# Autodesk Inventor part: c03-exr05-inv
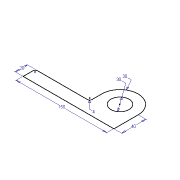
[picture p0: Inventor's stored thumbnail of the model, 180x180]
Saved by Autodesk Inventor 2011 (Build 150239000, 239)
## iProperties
Shininess: 64.0
Length Units: 11269
Angle Units: 11279
Time Units: 11290
Mass Units: 11283
Length Display Precision: 3
Angle Display Precision: 2
Compacted: True
Created: 2002-02
Part Number: c03-exr05-inv
Document SubType Name: Modeling
Density: 1 g/cm^3
Density: 0.0
Volumn: 0.0
Area: 0.0
PropertySet Name: Model Information
Control State: 0
Master: False
Checked Out: False
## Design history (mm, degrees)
sketch "Sketch1"
  geometry: L1 (-66.957, -29.14)-(83.043, -29.14); L2 (83.043, -29.14)-(83.043, 10.86); L3 (23.043, 10.86)-(23.043, -5.14); L4 (19.043, -9.14)-(-62.957, -9.14); L5 (-66.957, -13.14)-(-66.957, -29.14); C1 r 15 at (53.043, 10.86); A1 r 30 centre (53.043, 10.86) between (83.043, 10.86) and (23.043, 10.86); A2 r 4 centre (19.043, -5.14) between (19.043, -9.14) and (23.043, -5.14); A3 r 4 centre (-62.957, -13.14) between (-62.957, -9.14) and (-66.957, -13.14)
  constraints: 10 end point, 6 point on circle, 6 tangent, 4 centre point, 3 parallel, 1 coincident, 1 equal radius, 1 horizontal, 1 perpendicular
  dimensions: "d0" = 150 distance of L1.start L1.end; "d1" = 40 distance of L1.end L2.end; "d2" = 30 radius of A1; "d4" = 4 radius of A2; "d5" = 20 distance between parallel lines of L1 L4; "d6" = 30 diameter of C1
